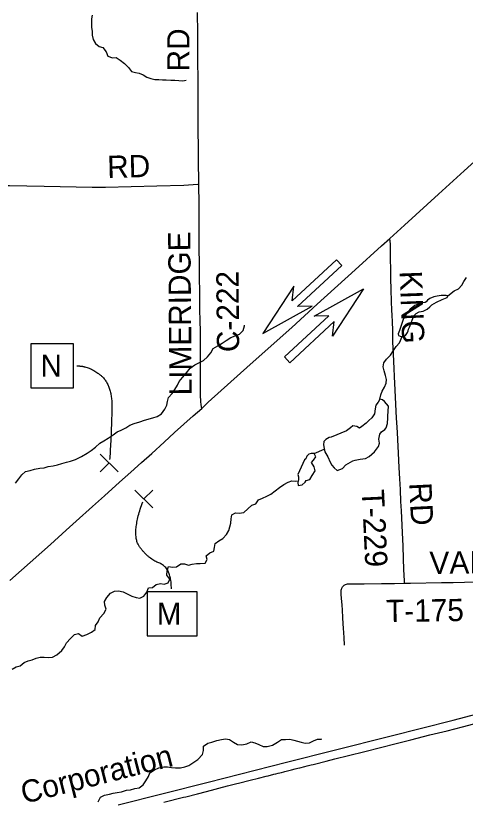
# Model space of a CAD drawing. Extents: x 0 to 34, y 0 to 22.
# Drawn here: x 9.804 to 12.669, y 9.413 to 14.409 of the extents above; entities that cross this region are included whole.
import ezdxf

# ---------------------------------------------------------------- set-up
doc = ezdxf.new("R2010")
doc.units = 0
for name, color, linetype in [('GM_X_County_Road', 7, 'Continuous'), ('GM_X_County_Road_Text', 7, 'Continuous'), ('GM_X_Minor_Lake', 7, 'Continuous'), ('GM_X_Minor_River', 7, 'Continuous'), ('GM_X_Rail_Line', 7, 'Continuous'), ('GM_X_Rail_Line_Text', 7, 'Continuous'), ('GM_X_State_Route', 7, 'Continuous'), ('GM_X_Township_Road', 7, 'Continuous'), ('GM_X_Township_Road_Text', 7, 'Continuous'), ('PM_P_Cells', 7, 'Continuous'), ('SH_Text', 7, 'Continuous'), ('SN_P_Signs', 7, 'Continuous')]:
    doc.layers.add(name, color=color, linetype=linetype)

msp = doc.modelspace()

# ---------------------------------------------------------------- linework, layer by layer
at = {"layer": 'GM_X_County_Road'}
for points in [[(10.9711, 13.3344), (10.9702, 13.3832), (10.9689, 13.4462), (10.9682, 13.5494), (10.967, 13.6969), (10.9659, 13.8119), (10.9659, 13.9066), (10.9656, 13.9703), (10.9656, 14.0403), (10.9651, 14.0837), (10.9648, 14.1785), (10.9647, 14.242), (10.964, 14.2962), (10.9639, 14.3443), (10.9633, 14.383), (10.9629, 14.4078), (10.9624, 14.4295)], [(10.9891, 11.9052), (10.9858, 11.9283), (10.9839, 11.9486), (10.9824, 11.9899), (10.9817, 12.0271), (10.9813, 12.0738), (10.9809, 12.1126), (10.9808, 12.1297), (10.9806, 12.1825), (10.9808, 12.2151), (10.9811, 12.2585), (10.9806, 12.308), (10.9811, 12.356), (10.9806, 12.4116), (10.9798, 12.4519), (10.9782, 12.5496), (10.9778, 12.5837), (10.9778, 12.6163), (10.9756, 12.7694), (10.9742, 12.8568), (10.9736, 12.8973), (10.9733, 13.0404), (10.972, 13.2201), (10.9713, 13.3196), (10.9711, 13.3344)]]:
    msp.add_lwpolyline(points, dxfattribs=at)
at = {"layer": 'GM_X_Minor_Lake'}
for p, q in [((12.313, 12.4227), (12.3406, 12.4952)), ((11.9113, 11.762), (11.8142, 11.7229)), ((11.6445, 11.5766), (11.601, 11.485))]:
    msp.add_line(p, q, dxfattribs=at)
for points in [[(12.3406, 12.4952), (12.3556, 12.5096), (12.3754, 12.5203), (12.4009, 12.5253), (12.4253, 12.5389), (12.4432, 12.5524), (12.4563, 12.5658), (12.4845, 12.5823), (12.5212, 12.5998), (12.5533, 12.6116), (12.5579, 12.624), (12.5475, 12.6258), (12.5153, 12.6244), (12.4888, 12.6213), (12.468, 12.6163), (12.4435, 12.6065), (12.4275, 12.5949), (12.4201, 12.5854), (12.4125, 12.5815), (12.388, 12.5774), (12.3672, 12.5705), (12.3474, 12.5608), (12.3343, 12.5502), (12.3174, 12.5376), (12.2969, 12.5127), (12.2755, 12.4783), (12.2626, 12.4411), (12.2498, 12.402), (12.2406, 12.381), (12.2426, 12.3706), (12.253, 12.3651), (12.2654, 12.3642), (12.288, 12.3712), (12.3001, 12.3884), (12.3038, 12.4008), (12.3075, 12.4103), (12.313, 12.4227)], [(11.8142, 11.7229), (11.801, 11.7189), (11.7794, 11.7082), (11.7682, 11.6939), (11.7646, 11.6729), (11.7687, 11.6502), (11.7736, 11.6284), (11.792, 11.5964), (11.8084, 11.5633), (11.8191, 11.5435), (11.8325, 11.5257), (11.8526, 11.5097), (11.8856, 11.5225), (11.9071, 11.5455), (11.9513, 11.5717), (11.9674, 11.5747), (11.9986, 11.5808), (12.0335, 11.5859), (12.0552, 11.5985), (12.0908, 11.6293), (12.1151, 11.6619), (12.1214, 11.6847), (12.1183, 11.7094), (12.1237, 11.7417), (12.1339, 11.7561), (12.1555, 11.7715), (12.1639, 11.7821), (12.1731, 11.8097), (12.1746, 11.8458), (12.1754, 11.8562), (12.1779, 11.8885), (12.1785, 11.9199), (12.1535, 11.95), (12.1401, 11.9602), (12.1249, 11.9648), (12.1138, 11.9448), (12.0979, 11.9265), (12.0934, 11.9027), (12.0891, 11.8714), (12.0733, 11.8455), (12.0536, 11.8282), (12.0367, 11.8119), (12.0095, 11.7907), (11.9935, 11.7791), (11.9782, 11.7894), (11.9526, 11.7938), (11.9367, 11.7813), (11.9113, 11.762)], [(11.601, 11.485), (11.6059, 11.4698), (11.6061, 11.4508), (11.6006, 11.4337), (11.6037, 11.4138), (11.6302, 11.4179), (11.648, 11.4361), (11.6545, 11.4467), (11.679, 11.4517), (11.692, 11.4775), (11.7125, 11.5081), (11.7056, 11.5337), (11.6882, 11.56), (11.7013, 11.5763), (11.7153, 11.5974), (11.7046, 11.6181), (11.6857, 11.6189), (11.6715, 11.613), (11.6584, 11.6005), (11.652, 11.5833), (11.6445, 11.5766)]]:
    msp.add_lwpolyline(points, dxfattribs=at)
at = {"layer": 'GM_X_Minor_River'}
for points in [[(10.292, 14.4134), (10.2866, 14.3897), (10.286, 14.3602), (10.2863, 14.3355), (10.2913, 14.309), (10.2916, 14.2853), (10.2985, 14.2569), (10.3121, 14.2314), (10.3359, 14.2118), (10.3597, 14.2054), (10.3799, 14.1781), (10.3915, 14.1507), (10.4201, 14.1397), (10.4447, 14.1418), (10.4704, 14.126), (10.4962, 14.1035), (10.523, 14.0782), (10.5413, 14.0528), (10.5669, 14.0465), (10.5916, 14.042), (10.6154, 14.0328), (10.6392, 14.0169), (10.6649, 14.0077), (10.6905, 14.0033)], [(10.6905, 14.0033), (10.7151, 14.0017), (10.7398, 14.001), (10.7634, 13.9994), (10.7928, 13.9988), (10.8184, 13.9982), (10.844, 13.9956), (10.8686, 13.994), (10.8904, 13.9971)], [(12.5579, 12.624), (12.5983, 12.6548), (12.6256, 12.6675), (12.6471, 12.6915), (12.6601, 12.7154), (12.6769, 12.7393)], [(10.7322, 11.8706), (10.7537, 11.9012), (10.7667, 11.9261), (10.7702, 11.9498), (10.7765, 11.9746), (10.8009, 12.0005), (10.8176, 12.0263), (10.8353, 12.0531), (10.8445, 12.0779), (10.8669, 12.1029), (10.8912, 12.1316), (10.9146, 12.1613), (10.9456, 12.1835), (10.971, 12.1952), (11.0011, 12.2108), (11.0255, 12.2348), (11.0479, 12.2597), (11.0628, 12.2875), (11.0919, 12.3039), (11.1192, 12.3213), (11.1446, 12.3378), (11.1747, 12.3571), (11.202, 12.3679), (11.2303, 12.3777), (11.2537, 12.4027), (11.2619, 12.4312), (11.2628, 12.436)], [(12.1249, 11.9648), (12.1313, 11.9924), (12.1386, 12.0162), (12.1535, 12.0402), (12.1636, 12.0669), (12.1662, 12.0906), (12.1592, 12.1162), (12.1514, 12.1446), (12.1463, 12.1711), (12.1489, 12.1958), (12.1666, 12.2197), (12.191, 12.2438), (12.2105, 12.2744), (12.2282, 12.2993), (12.2497, 12.3232), (12.2654, 12.3642)], [(9.8026, 11.4296), (9.8231, 11.4564), (9.8427, 11.4823), (9.8671, 11.5035), (9.8955, 11.5095), (9.9247, 11.5184), (9.9587, 11.5245), (9.9862, 11.5267), (10.0116, 11.5346), (10.0428, 11.5397), (10.0702, 11.5467), (10.0976, 11.5546), (10.1278, 11.5616), (10.1533, 11.5685), (10.1854, 11.5794), (10.223, 11.5988), (10.2588, 11.6201), (10.2851, 11.6366), (10.3133, 11.6587), (10.3404, 11.6828), (10.3658, 11.6992), (10.3922, 11.7156), (10.425, 11.7379), (10.4504, 11.7553), (10.4768, 11.766), (10.506, 11.7825), (10.5314, 11.7989), (10.5596, 11.8097), (10.5946, 11.8196), (10.6238, 11.8294), (10.6785, 11.8453), (10.7059, 11.8542), (10.7322, 11.8706)], [(11.7046, 11.6181), (11.7698, 11.6454)], [(10.3659, 10.5971), (10.3797, 10.6248), (10.3719, 10.6503), (10.3697, 10.674), (10.3855, 10.7008), (10.4089, 10.7267), (10.4343, 10.7394), (10.4589, 10.7415), (10.4893, 10.7353), (10.5188, 10.7214), (10.5445, 10.7084), (10.5711, 10.6992), (10.5948, 10.6947), (10.6203, 10.7074), (10.6389, 10.7342), (10.6509, 10.7609), (10.6755, 10.7631), (10.6999, 10.7824), (10.7264, 10.7884), (10.7501, 10.7848), (10.7755, 10.7937), (10.7857, 10.8175), (10.7665, 10.8429), (10.7699, 10.8696), (10.7772, 10.8972), (10.8038, 10.8937), (10.8284, 10.8959), (10.8556, 10.9152), (10.8802, 10.9155), (10.904, 10.9063), (10.9285, 10.9132), (10.955, 10.9163), (10.9796, 10.9157), (11.0118, 10.918), (11.0229, 10.9418), (11.0169, 10.9664), (11.0414, 10.9838), (11.0658, 10.9955), (11.0703, 11.0193), (11.0748, 11.045), (11.0992, 11.0604), (11.1246, 11.0769), (11.147, 11.1018), (11.1619, 11.1267), (11.1692, 11.1505), (11.1737, 11.1743), (11.1762, 11.2018), (11.1807, 11.2266), (11.2051, 11.2401), (11.2288, 11.2376), (11.2581, 11.2427), (11.2825, 11.2648), (11.3088, 11.2879), (11.3342, 11.2967), (11.35, 11.3216), (11.3755, 11.3342), (11.4037, 11.3459), (11.4291, 11.3595), (11.4564, 11.3807), (11.4855, 11.4001), (11.5118, 11.4194), (11.5391, 11.4358), (11.5636, 11.4447), (11.5883, 11.4411), (11.604, 11.4443)], [(9.7818, 10.2438), (9.8063, 10.2583), (9.8327, 10.2643), (9.859, 10.2855), (9.8845, 10.2953), (9.9099, 10.3022), (9.9344, 10.313), (9.9599, 10.3199), (9.9845, 10.3202), (10.013, 10.3167), (10.0395, 10.319), (10.0658, 10.3354), (10.0977, 10.3614), (10.1154, 10.3863), (10.1274, 10.4111), (10.1527, 10.438), (10.1789, 10.4639), (10.2035, 10.4699), (10.2273, 10.4531), (10.2575, 10.4648), (10.2867, 10.4785), (10.3111, 10.4968), (10.3118, 10.5205), (10.3286, 10.5454), (10.3406, 10.5693), (10.3659, 10.5971)], [(10.3301, 9.3979), (10.344, 9.4275), (10.3694, 9.4391), (10.4006, 9.4471), (10.4251, 9.4531), (10.4506, 9.4572), (10.478, 9.4613), (10.5092, 9.4721), (10.5357, 9.4743), (10.563, 9.4813), (10.5914, 9.4873), (10.6158, 9.5056), (10.6335, 9.5305), (10.6502, 9.5592), (10.6594, 9.583), (10.6886, 9.6004), (10.7168, 9.6141), (10.7471, 9.6201), (10.7717, 9.6195), (10.7963, 9.616), (10.8229, 9.6134), (10.8541, 9.6138), (10.8815, 9.6198), (10.9079, 9.6287), (10.9333, 9.6451), (10.9643, 9.6673), (10.9952, 9.6999), (11.0015, 9.7247), (11.0003, 9.7512), (11.0285, 9.7715), (11.054, 9.7775), (11.0851, 9.7873), (11.1153, 9.7953), (11.1408, 9.7994), (11.1664, 9.794), (11.1912, 9.7782), (11.2179, 9.7633), (11.2445, 9.7607), (11.2756, 9.7659), (11.3048, 9.7804), (11.3286, 9.7741), (11.3533, 9.762), (11.38, 9.75), (11.4055, 9.7503), (11.4395, 9.7583), (11.4715, 9.7786), (11.4978, 9.7941), (11.5234, 9.7944), (11.5499, 9.7957), (11.5755, 9.7902), (11.5993, 9.7839), (11.623, 9.7766), (11.6486, 9.7702), (11.6751, 9.7743), (11.7005, 9.786), (11.726, 9.7958), (11.7516, 9.7971), (11.7534, 9.798)]]:
    msp.add_lwpolyline(points, dxfattribs=at)
at = {"layer": 'GM_X_Rail_Line'}
msp.add_lwpolyline([(10.456, 9.3774), (11.0307, 9.523), (11.5302, 9.6495), (11.8337, 9.7264), (12.1885, 9.8167), (12.5923, 9.9184), (12.7448, 9.9584)], dxfattribs=at)
at = {"layer": 'GM_X_State_Route'}
msp.add_lwpolyline([(9.7675, 10.8081), (9.8403, 10.874), (10.0247, 11.0379), (10.1251, 11.1284), (10.1896, 11.1869), (10.2923, 11.2795), (10.3699, 11.3489), (10.4657, 11.4353), (10.537, 11.4987), (10.6057, 11.5611), (10.6707, 11.6186), (10.75, 11.6908), (10.8168, 11.7513), (10.9349, 11.857), (10.9891, 11.9052), (11.0309, 11.9449), (11.298, 12.1846), (11.5627, 12.4221), (11.7256, 12.5708), (11.9666, 12.7883), (12.1356, 12.9412), (12.1886, 12.9893), (12.2806, 13.0728), (12.4985, 13.272), (12.6608, 13.4192), (12.7745, 13.523)], dxfattribs=at)
at = {"layer": 'GM_X_Township_Road'}
for points in [[(9.7394, 13.3269), (9.7647, 13.3266), (9.9863, 13.3215), (10.2921, 13.3151), (10.3764, 13.3155), (10.7029, 13.325), (10.8754, 13.3292), (10.9638, 13.334), (10.9711, 13.3344)], [(12.2808, 10.7916), (12.2806, 10.8053), (12.2778, 10.878), (12.2748, 10.9493), (12.2717, 11.0267), (12.2681, 11.1142), (12.2621, 11.2516), (12.2587, 11.3121), (12.2572, 11.3369), (12.2559, 11.3617), (12.2547, 11.3881), (12.2536, 11.4222), (12.2522, 11.4564), (12.2475, 11.5276), (12.2439, 11.6208), (12.2391, 11.7061), (12.2361, 11.7526), (12.2324, 11.8161), (12.2307, 11.844), (12.2265, 11.9331), (12.2223, 12.0224), (12.2177, 12.1087), (12.2151, 12.1593), (12.2108, 12.2509), (12.2077, 12.3296), (12.2059, 12.4025), (12.2038, 12.4599), (12.2025, 12.4987), (12.2013, 12.5344), (12.1991, 12.5855), (12.1954, 12.6662), (12.1939, 12.7313), (12.1934, 12.7592), (12.1932, 12.795), (12.1926, 12.854), (12.1922, 12.8912), (12.1921, 12.9311), (12.1914, 12.9518), (12.1903, 12.9706), (12.1886, 12.9893)], [(11.9606, 10.7868), (12.0239, 10.7871), (12.1339, 10.7882), (12.2172, 10.7897), (12.2808, 10.7916)], [(12.2808, 10.7916), (12.3191, 10.7916), (12.5174, 10.795), (12.5921, 10.7955), (12.6641, 10.7971), (12.8668, 10.7995), (12.9825, 10.8022), (13.0382, 10.8035), (13.2055, 10.8053), (13.2934, 10.8068), (13.4168, 10.8092), (13.5755, 10.8112), (13.672, 10.8129), (13.8598, 10.8171), (13.9255, 10.8183), (14.0403, 10.8199), (14.0775, 10.8205), (14.095, 10.8211), (14.1069, 10.8225), (14.1174, 10.824), (14.1273, 10.8257), (14.1314, 10.8269)], [(11.8925, 10.5048), (11.891, 10.5323), (11.889, 10.5733), (11.8864, 10.6186), (11.8834, 10.6524), (11.8803, 10.6942), (11.8784, 10.7206), (11.8781, 10.7379), (11.8787, 10.7459), (11.8798, 10.7523), (11.8809, 10.7563), (11.8823, 10.76), (11.8862, 10.7672), (11.8901, 10.7724), (11.8947, 10.7771), (11.8973, 10.7789)], [(11.8973, 10.7789), (11.9001, 10.7809), (11.9046, 10.7831), (11.9108, 10.785), (11.9172, 10.7861), (11.9237, 10.7866), (11.9302, 10.7866), (11.9606, 10.7868)], [(11.8997, 10.3967), (11.8958, 10.4447), (11.8925, 10.5048)], [(10.748, 9.3941), (10.8728, 9.4261), (10.8879, 9.4298), (10.9631, 9.449), (11.0202, 9.4634), (11.1536, 9.4984), (11.2136, 9.5142), (11.2226, 9.5165), (11.2979, 9.5352), (11.3506, 9.5482), (11.4003, 9.5608), (11.4123, 9.5639), (11.4485, 9.5729), (11.4605, 9.5759), (11.477, 9.5801), (11.4966, 9.5849), (11.5131, 9.589), (11.5192, 9.5905), (11.5433, 9.5964), (11.5613, 9.601), (11.5839, 9.6066), (11.602, 9.6112), (11.614, 9.6143), (11.6456, 9.6223), (11.6606, 9.6261), (11.6862, 9.6326), (11.6983, 9.6357), (11.7073, 9.6379), (11.7825, 9.6568), (11.8365, 9.6706), (11.9234, 9.6934), (12.0285, 9.7188), (12.2275, 9.7693), (12.3213, 9.7928), (12.4429, 9.8236), (12.553, 9.8498), (12.6507, 9.8745), (12.7554, 9.9019)]]:
    msp.add_lwpolyline(points, dxfattribs=at)
at = {"layer": 'PM_P_Cells'}
for p, q in [((11.8483, 12.8534), (11.5663, 12.5912)), ((11.8823, 12.8168), (11.8483, 12.8534)), ((11.6004, 12.5546), (11.8823, 12.8168)), ((11.8653, 12.8351), (11.8653, 12.8351)), ((11.5755, 12.6841), (11.3784, 12.3822)), ((11.5663, 12.5912), (11.5755, 12.6841)), ((11.7052, 12.4933), (12.0206, 12.6681)), ((12.0206, 12.6681), (11.8234, 12.3662)), ((12.0206, 12.6681), (12.0206, 12.6681)), ((11.3784, 12.3822), (11.6938, 12.557)), ((11.6938, 12.557), (11.6004, 12.5546)), ((11.5166, 12.2335), (11.7985, 12.4957)), ((11.7985, 12.4957), (11.7052, 12.4933)), ((11.8326, 12.4591), (11.5507, 12.1969)), ((11.8234, 12.3662), (11.8326, 12.4591)), ((11.3784, 12.3822), (11.3784, 12.3822)), ((11.5507, 12.1969), (11.5166, 12.2335)), ((11.5336, 12.2152), (11.5336, 12.2152))]:
    msp.add_line(p, q, dxfattribs=at)
at = {"layer": 'SH_Text'}
for points in [[(9.9009, 12.0374), (10.1732, 12.0374), (10.1732, 12.3178), (9.9009, 12.3178)], [(10.6424, 10.4559), (10.9601, 10.4559), (10.9601, 10.7359), (10.6424, 10.7359)]]:
    msp.add_lwpolyline(points, close=True, dxfattribs=at)
for points in [[(10.1939, 12.1766), (10.2736, 12.1766), (10.4164, 12.057), (10.4164, 11.7978), (10.4027, 11.5791)], [(10.7959, 10.7557), (10.7959, 10.8886), (10.646, 10.9475), (10.5379, 11.1032), (10.6138, 11.3101)]]:
    msp.add_open_spline(points, degree=2, dxfattribs=at)
at = {"layer": 'SN_P_Signs'}
for p, q in [((10.3422, 11.6142), (10.4559, 11.5017)), ((10.399, 11.558), (10.3428, 11.5011)), ((10.6775, 11.272), (10.5637, 11.3845)), ((10.6206, 11.3282), (10.6768, 11.3851))]:
    msp.add_line(p, q, dxfattribs=at)

# ---------------------------------------------------------------- texts
at = {"layer": 'GM_X_County_Road_Text'}
for s, rotation, p in [('RD', 90, (10.9113, 14.0537)), ('LIMERIDGE', 90.4971, (10.9258, 11.9891)), ('C-222', 90.55, (11.2285, 12.2649))]:
    msp.add_text(s, height=0.14205, rotation=rotation, dxfattribs=at).set_placement(p)
at = {"layer": 'GM_X_Rail_Line_Text'}
msp.add_text('Corporation', height=0.141572, rotation=14.294, dxfattribs=at).set_placement((9.857, 9.3834))
at = {"layer": 'GM_X_Township_Road_Text'}
for s, rotation, p in [('RD', 1.4826, (10.3886, 13.3741)), ('KING', 272.1292, (12.2501, 12.7804)), ('RD', 272.9086, (12.3105, 11.4292)), ('T-229', 272.7288, (12.0085, 11.386)), ('VAIR', 0.8423, (12.4414, 10.8492)), ('T-175', 0.8421, (12.1642, 10.5426))]:
    msp.add_text(s, height=0.14205, rotation=rotation, dxfattribs=at).set_placement(p)
at = {"layer": 'SH_Text'}
for s, p in [('N', (9.9621, 12.1081)), ('M', (10.7036, 10.5266))]:
    msp.add_text(s, height=0.14, dxfattribs=at).set_placement(p)

doc.saveas('drawing.dxf')
